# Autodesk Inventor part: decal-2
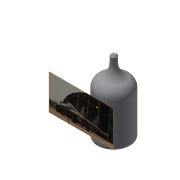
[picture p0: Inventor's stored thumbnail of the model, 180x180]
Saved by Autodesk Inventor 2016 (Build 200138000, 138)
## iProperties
Shininess: 64.0
Length Units: 11269
Angle Units: 11279
Time Units: 11290
Mass Units: 11283
Length Display Precision: 3
Angle Display Precision: 2
Compacted: True
Part Number: decal-2
Document SubType Name: Modeling
Created: 2002-12
Designer: deepak
Material: Generic
Density: 1 g/cm^3
Appearance: Default
Density: 0.0
Volumn: 0.0
Area: 0.0
PropertySet Name: Model Information
Control State: 0
Master: False
Checked Out: False
Author: deepak
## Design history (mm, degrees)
node "Sketch1"
sketch "Sketch2"
  geometry: L1 (2.054, 26.655)-(2.054, 21.177); L2 (11.64, 6.114)-(11.64, -24.209); L3 (11.64, -24.209)-(-0.098, -24.209); L4 (-0.098, -24.209)-(-0.098, 26.655); L5 (-0.098, 26.655)-(2.054, 26.655); A1 r 9.502 centre (11.556, 21.177) between (2.054, 21.177) and (7.532, 12.57); A2 r 7.127 centre (4.514, 6.114) between (11.64, 6.114) and (7.532, 12.57)
  constraints: 10 end point, 4 point on circle, 3 parallel, 3 tangent, 2 centre point, 1 perpendicular, 1 vertical
revolve "Revolution1" sketch "Sketch2" stored, may be unused: angle "d0" = 90 deg
fillet "Fillet1" dims "d1" = 2
chamfer "Chamfer1" distance "d2" = 1; stored, may be unused: second distance "d3" = 2, angle "d21" = 45 deg
workplane "Work Plane4"
sketch "Sketch7"
  geometry: L1 (-11.326, 14.075)-(33.849, 14.075); L2 (33.849, 14.075)-(33.849, -10.781); L3 (33.849, -10.781)-(-11.326, -10.781); L4 (-11.326, -10.781)-(-11.326, 14.075); 1 further point; 1 other entity
  constraints: 2 other
  node "Image6"
body "Solid1"
